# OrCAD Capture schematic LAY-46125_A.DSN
size A3; rev: 1; note: ANTENNA MODULE (With uFL)
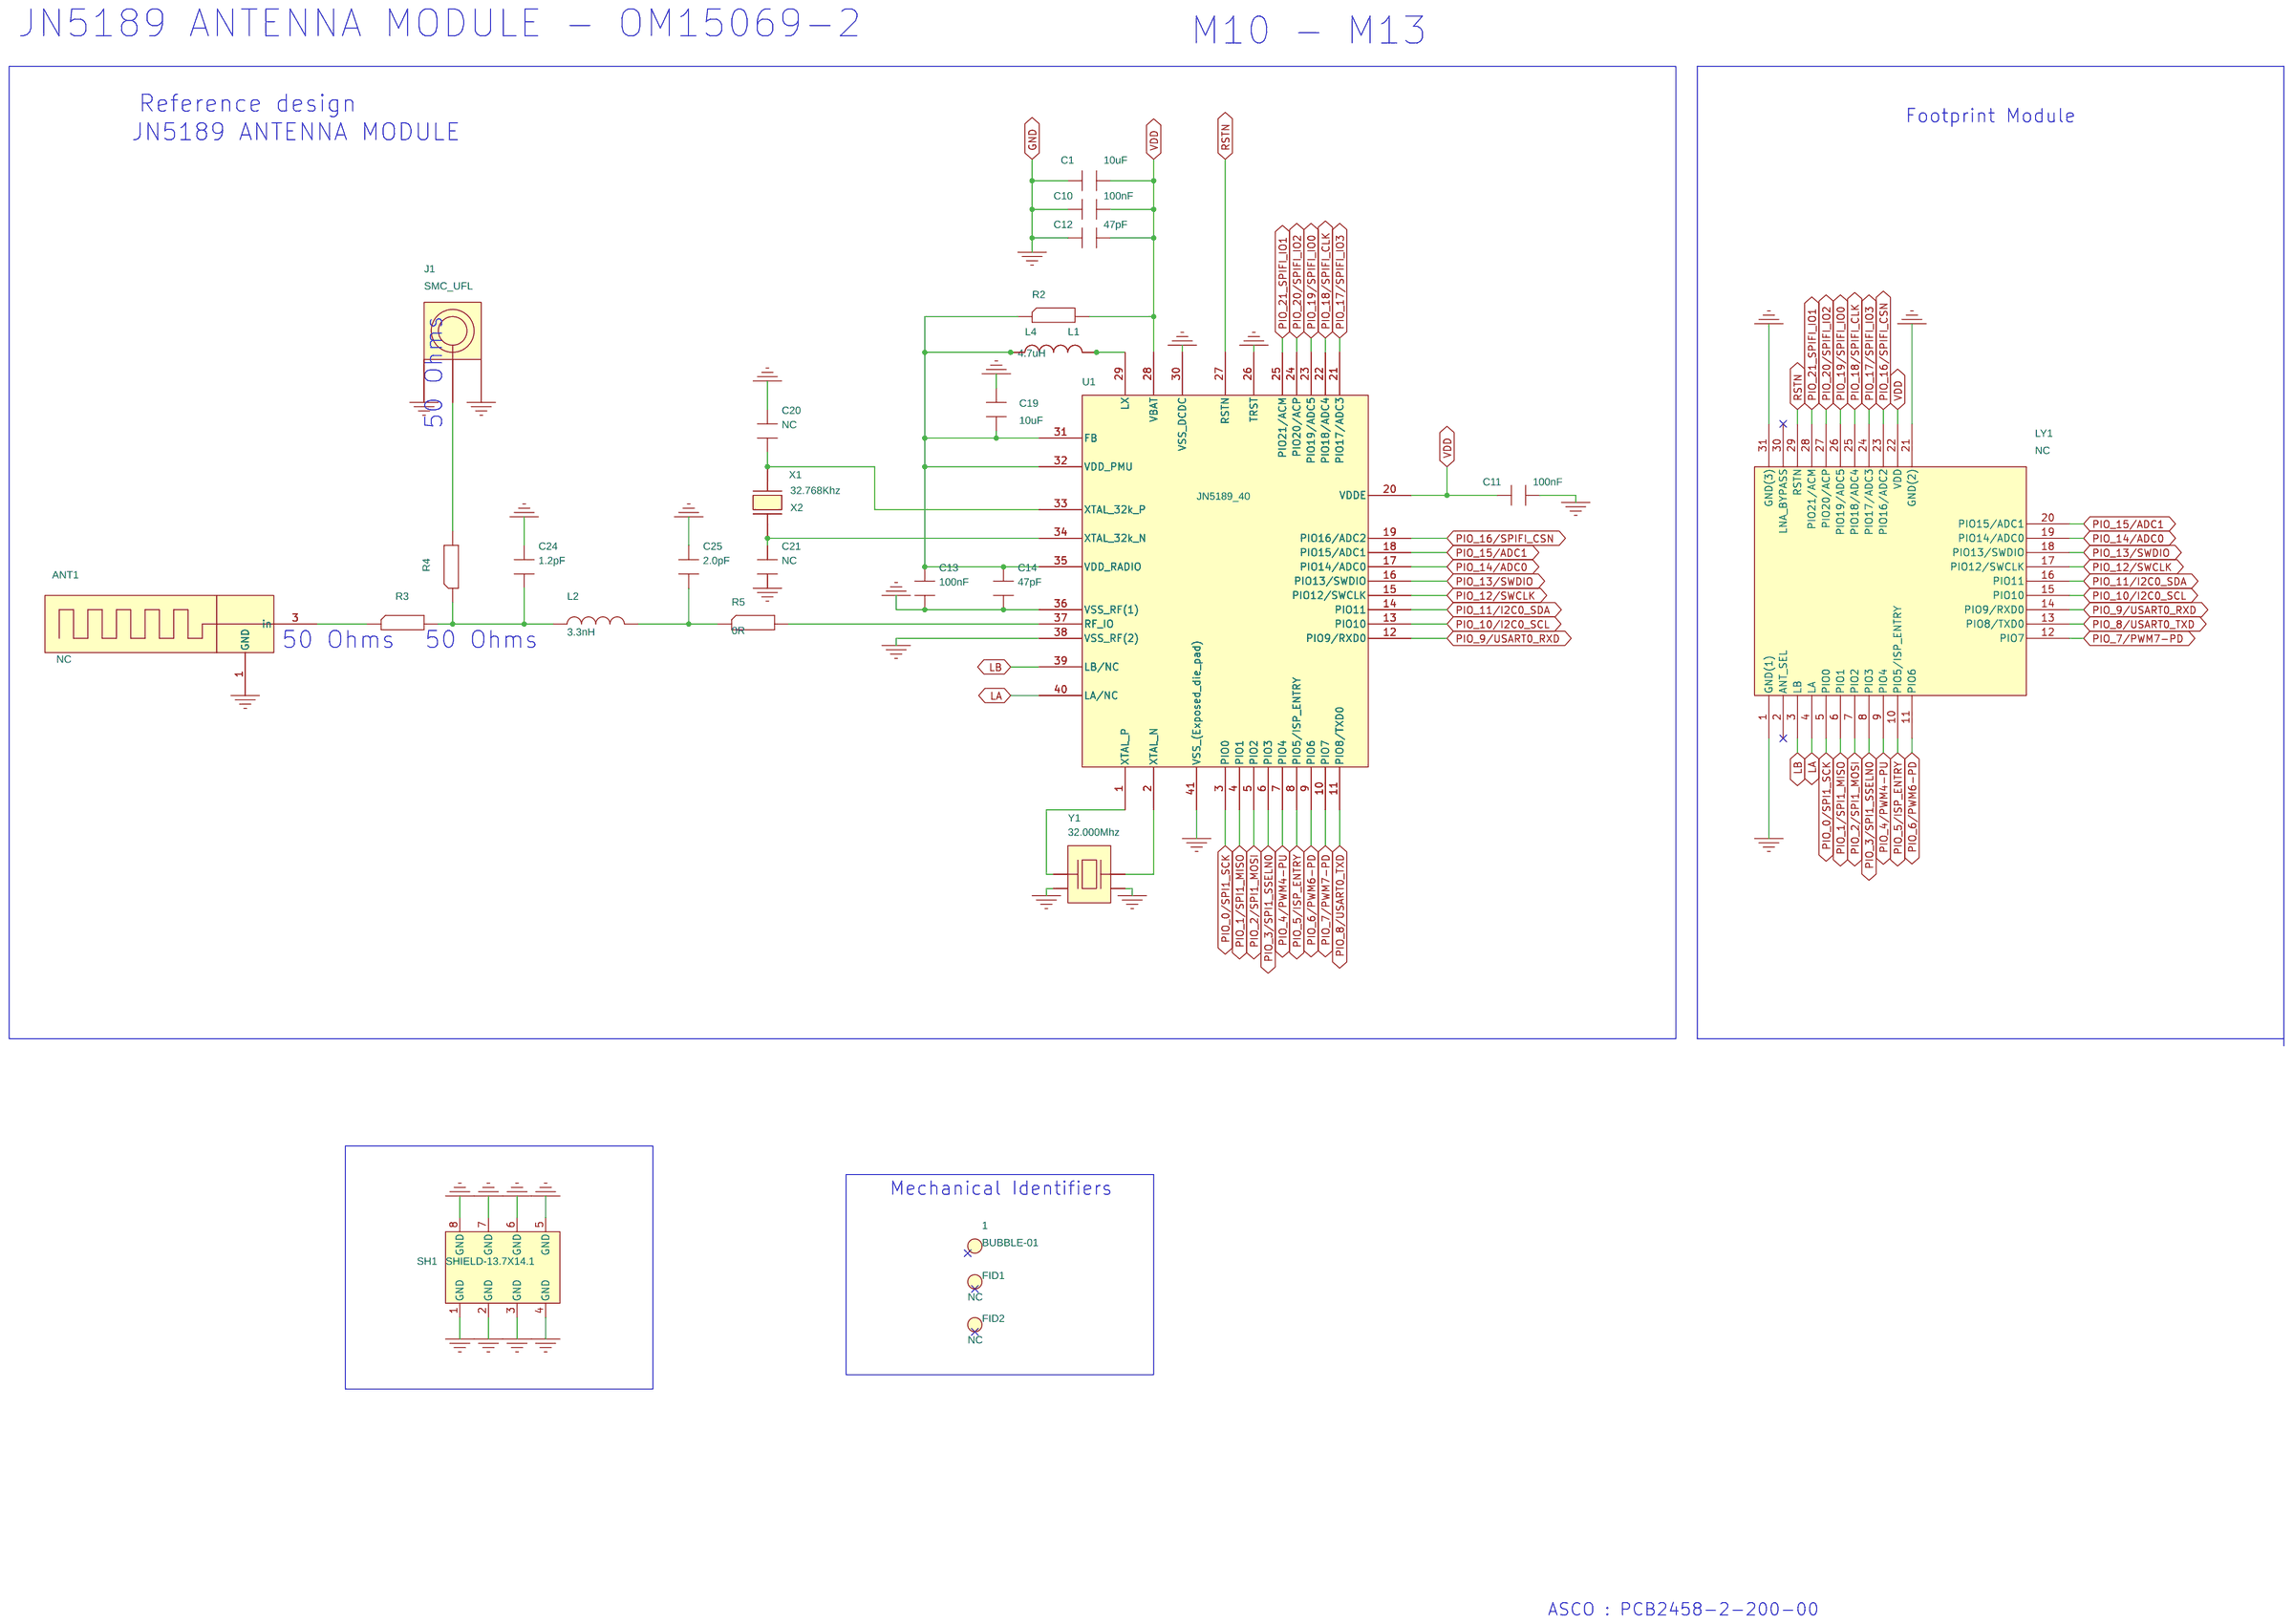
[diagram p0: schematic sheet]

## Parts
1  BUBBLE-01  [BUBBLE_DIAM8]
ANT1  NC  [pcb_ant_apps]
C1  10uF  [C0805]
C10  100nF  [C0402]
C11  100nF  [C0402]
C12  47pF  [C0402]
C13  100nF  [C0402]
C14  47pF  [C0402]
C19  10uF  [C0805]
C20  NC  [C0402]
C21  NC  [C0402]
C24  1.2pF  [C0402]
C25  2.0pF  [C0402]
FID1  NC  [FID1]
FID2  NC  [FID1]
J1  SMC_UFL  [SMC-UFL-R-SMT]
L1  4,7uH_NC  [IND_CB_2518_2520]
L2  3.3nH  [SELF_0402]
L4  4.7uH  [0805C_IPCC]
LY1  NC  [LYRE_31PTS_CARRIER]
R2  NC  [R0402]
R3  0R  [R0402]
R4  NC  [R0402]
R5  0R  [R0402]
SH1  SHIELD-13.7X14.1  [shield_13mm7x14mm1]
U1  JN5189_40  [SOT618-1_HVQFN40_050_JN518x]
X1  32.768Khz_NC  [NX3215SA]
X2  32.768Khz  [NX2012SA]
Y1  32.000Mhz  [NX2016SA]

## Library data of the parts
1 = BUBBLE: Designation: Printed Circuit Board : OM15069-2 (NXP : module JN5189 (HVQFN40) With PCB Antenna + Connector uFL); Manufacturer_reference: PCB2458-2; Part Number: 0-CI-001587; Part Type: BUBBLE-001_CI; Supplier: ASCO
ANT1 = ANTENNA_JN518x: Alt_Symbols: pcb_ant_apps_flip; Designation: !!! COPPER PRINTED BOARD !!!; Package: ANTENNA; Part Number: 0-00-0ANT_MOD_JN518x; Part Type: MISC
C1 C19 = CAPA: Alt_Symbols: 0805C; Designation: Capacitor 0805 10uF 10% 10V X7R (-55°C+125°C); Gamme: X7R; MANUFACTURER_REFERENCE: MURATA (GRM21BR71A106KA73L); Package: 805; Part Number: 0-00-306046A; Supplier: FARNELL; Tension: 10V; Tol: 10%
C10 C11 C13 = CAPA: Alt_Symbols: 0402C; Designation: Capacitor 0402 100nF 5% 10V X7R (-55°C+125°C); Gamme: X7R; MANUFACTURER_REFERENCE: MURATA (GRM155R71A104JA01#); Package: 402; Part Number: 0-00-305250A; Tension: 10V; Tol: 5%
C12 C14 = CAPA: Alt_Symbols: 0402C; Designation: Capacitor 0402 47pF 5% 25V COG/NPO (-55°C+125°C); Gamme: COG/NPO; MANUFACTURER_REFERENCE: MURATA (GRM1555C1E470JA01); Package: 402; Part Number: 0-00-300164C; Supplier: DIGIKEY CORPORATION; Temp: (-55°C+125°C); Tension: 25V; Tol: 5%
C20 C21 = CAPA: Alt_Symbols: 0402C; Designation: !!! NOT CONNECTED !!!; Package: 402; Part Number: 0-00-3NC_C0402
C24 = CAPA: Alt_Symbols: 0402C; Designation: Capacitor 0402 1.2pF +/-0.1pF 50V; MANUFACTURER_REFERENCE: MURATA (GRM1555C1H1R2BA01D); Package: 402; Part Number: 0-00-300040A; Supplier: RADIOSPARES; Tension: 50V; Tol: +/-0.1pF
C25 = CAPA: Alt_Symbols: 0402C; Designation: Capacitor 0402 2.0pF +/-0.1pF 50V; Package: 402; Part Number: 0-00-305251; Tension: 50V; Tol: +/-0.1pF
FID1 FID2 = MIRE: Designation: !!! Not Connected !!!; Part Number: 0-00-2MIRE_FID_NC; Part Type: MISC
J1 = SMC_UFL: Designation: Coaxial Connector SMC (uFL); Manufacturer_reference: HIROSE (U.FL-R-SMT-1(10)), Hirose Electric Co Ltd (U.FL-R-SMT-1(10)), HRS (HIROSE) (U.FL-R-SMT-1(10)); Part Number: 0-00-201187A; Part Type: CONNECTOR
L1 = SELF: Designation: !!! NOT CONNECTED !!! Inductor 1008/2520 4,7uH 800mA(Max) 380mOhms(Max) 20%; Manufacturer_reference: TAIYO YUDEN (MBMK2520H4R7M); Package: 1008; Part Number: 0-00-002246A_NC; Part Type: INDUCTOR
L2 = SELF: Designation: Inductor 0402 3.3nH +/-0.1nH 2A, Ron DC=30mOhms, Q=30, Resonance Freq=14.0 Ghz (-55°C to 125°C); Manufacturer_reference: MURATA (LQW15AN3N3B); Package: 402; Part Number: PN-LQW15AN3N3B; Part Type: L0402; Temp: (-55°C to 125°C)
L4 = SELF: Designation: Inductor 0805 4,7uH 300mA(Max) 340mOhms(Max) 20% (-55°C to 125°C); Manufacturer_reference: TDK (MLZ2012M4R7H); Package: 805; Part Number: 0-00-002803A; Part Type: L0805
LY1 = LYRE_MODJN518x_31PTS: Designation: !!! Not Connected !!!; Manufacturer_reference: NXP; Package: LYRE; Part Number: 0-00-2LYREMODJN518x_31_NC; Part Type: LYRE
R2 R4 = RES: Designation: !!! NOT CONNECTED !!!; PACKAGE: 402; Part Number: 0-00-3NC_R0402
R3 R5 = RES: Alt_Symbols: 0402R; Designation: Resistor 0402 0R - - -; PACKAGE: 402; Part Number: 0-00-301956; Type: CMS
SH1 = SHIELD_8PTS: Designation: !!! NOT CONNECTED !!! SHIELD : 13.7MM x 14.1MM; Manufacturer_reference: NXP; Package: SHIELD; Part Number: NC-0-00-204888; Part Type: SHIELD
U1 = JN518x_QFN40: Designation: Integrated Circuit JN5189 (QFN40); Manufacturer_reference: NXP (JN5189) (QFN40); Package: HVQFN40; Part Number: 0-00-404672; Part Type: IC
X1 = XTAL: Designation: !!! NOT CONNECTED !!! Crystal 32.768 KHz +/-20ppm (Automotive version) (Load Cap. 12.5pF) (-40°C to 125°C); Manufacturer_reference: NDK (NX3215SA-32.768K-STD-MUS-2); Part Number: 0-00-403987_NC; Part Type: CLOCK; Temp: (-40°C to 125°C)
X2 = XTAL: Designation: Crystal 32.768 KHz +/-20ppm (Automotive version) (Load Cap. 6.0pF) (-40°C to 125°C); Manufacturer_reference: NDK (NX2012SA 32.768KHZ EXS00A-MU01089 6pF); Part Number: 0-00-404675; Part Type: CLOCK
Y1 = XTAL_NX2016_4P: Designation: Crystal 32 MHz +/-40ppm (automotive version) (Load Cap. 6.0pF) (-40°C to 125°C); Manufacturer_reference: NDK (NX2016SA 32MHZ EXS00A-CS11213 6PF); Part Number: 0-00-404674; Part Type: CLOCK

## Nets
GND: ANT1.1(GND) C1.1 C10.1 C11.2 C12.1 C13.2 C14.2 C19.2 C20.1 C21.2 C24.1 C25.1 J1.2 J1.3 LY1.1(GND(1)) LY1.21(GND(2)) LY1.31(GND(3)) SH1.1(GND) SH1.2(GND) SH1.3(GND) SH1.4(GND) SH1.5(GND) SH1.6(GND) SH1.7(GND) SH1.8(GND) U1.26(TRST) U1.30(VSS_DCDC) U1.36(VSS_RF(1)) U1.38(VSS_RF(2)) U1.41(VSS_(Exposed_die_pad)) Y1.2 Y1.4
VDD: C1.2 C10.2 C11.1 C12.2 LY1.22(VDD) R2.2 U1.20(VDDE) U1.28(VBAT)
LA: LY1.4(LA) U1.40(LA/NC)
LB: LY1.3(LB) U1.39(LB/NC)
PIO_0/SPI1_SCK: LY1.5(PIO0) U1.3(PIO0)
PIO_1/SPI1_MISO: LY1.6(PIO1) U1.4(PIO1)
PIO_2/SPI1_MOSI: LY1.7(PIO2) U1.5(PIO2)
PIO_3/SPI1_SSELN0: LY1.8(PIO3) U1.6(PIO3)
PIO_4/PWM4-PU: LY1.9(PIO4) U1.7(PIO4)
PIO_5/ISP_ENTRY: LY1.10(PIO5/ISP_ENTRY) U1.8(PIO5/ISP_ENTRY)
PIO_6/PWM6-PD: LY1.11(PIO6) U1.9(PIO6)
PIO_7/PWM7-PD: LY1.12(PIO7) U1.10(PIO7)
PIO_8/USART0_TXD: LY1.13(PIO8/TXD0) U1.11(PIO8/TXD0)
PIO_9/USART0_RXD: LY1.14(PIO9/RXD0) U1.12(PIO9/RXD0)
PIO_10/I2C0_SCL: LY1.15(PIO10) U1.13(PIO10)
PIO_11/I2C0_SDA: LY1.16(PIO11) U1.14(PIO11)
PIO_12/SWCLK: LY1.17(PIO12/SWCLK) U1.15(PIO12/SWCLK)
PIO_13/SWDIO: LY1.18(PIO13/SWDIO) U1.16(PIO13/SWDIO)
PIO_14/ADC0: LY1.19(PIO14/ADC0) U1.17(PIO14/ADC0)
PIO_15/ADC1: LY1.20(PIO15/ADC1) U1.18(PIO15/ADC1)
PIO_16/SPIFI_CSN: LY1.23(PIO16/ADC2) U1.19(PIO16/ADC2)
PIO_17/SPIFI_IO3: LY1.24(PIO17/ADC3) U1.21(PIO17/ADC3)
PIO_18/SPIFI_CLK: LY1.25(PIO18/ADC4) U1.22(PIO18/ADC4)
PIO_19/SPIFI_IO0: LY1.26(PIO19/ADC5) U1.23(PIO19/ADC5)
PIO_20/SPIFI_IO2: LY1.27(PIO20/ACP) U1.24(PIO20/ACP)
PIO_21_SPIFI_IO1: LY1.28(PIO21/ACM) U1.25(PIO21/ACM)
RSTN: LY1.29(RSTN) U1.27(RSTN)
N16830681: U1.1(XTAL_P) Y1.1
N16830709: C24.2 L2.1 R3.2 R4.1
N16830719: C25.2 L2.2 R5.1
N16830729: R5.2 U1.37(RF_IO)
N16830755: C13.1 C14.1 C19.1 L1.1 L4.1 R2.1 U1.31(FB) U1.32(VDD_PMU) U1.35(VDD_RADIO)
N16830775: C20.2 U1.33(XTAL_32k_P) X1.1 X2.1
N16830789: L1.2 L4.2 U1.29(LX)
N16832469: C21.1 U1.34(XTAL_32k_N) X1.2 X2.2
N16842652: U1.2(XTAL_N) Y1.3
N16849423: J1.1 R4.2
N16850832: ANT1.3(in) R3.1

Not connected (* = marked no-connect by the designer): 1 1*; FID1 1*; FID2 1*; LY1 2(ANT_SEL)* 30(LNA_BYPASS)*

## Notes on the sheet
- JN5189 ANTENNA MODULE - OM15069-2
- M10 - M13
- Reference design
- Footprint Module
- JN5189 ANTENNA MODULE
- 50 Ohms
- 50 Ohms
- 50 Ohms
- Mechanical Identifiers
- ASCO : PCB2458-2-200-00
